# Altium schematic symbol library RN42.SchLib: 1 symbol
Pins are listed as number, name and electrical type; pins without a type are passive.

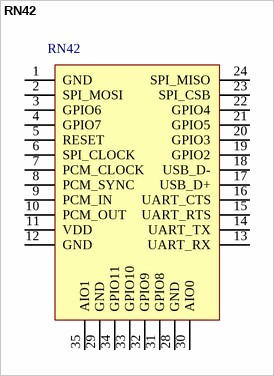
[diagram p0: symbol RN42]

## RN42
designator RN42  (value not drawn)
RN42 Bluetooth Transciever
footprint RN42 (RN42 Bluetooth Transciever)
pins: 1 GND, 2 SPI_MOSI, 3 GPIO6, 4 GPIO7, 5 RESET, 6 SPI_CLOCK, 7 PCM_CLOCK, 8 PCM_SYNC, 9 PCM_IN, 10 PCM_OUT, 11 VDD, 12 GND, 13 UART_RX, 14 UART_TX, 15 UART_RTS, 16 UART_CTS, 17 USB_D+, 18 USB_D-, 19 GPIO2, 20 GPIO3, 21 GPIO5, 22 GPIO4, 23 SPI_CSB, 24 SPI_MISO, 28 GND, 29 GND, 30 AIO0, 31 GPIO8, 32 GPIO9, 33 GPIO10, 34 GPIO11, 35 AIO1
